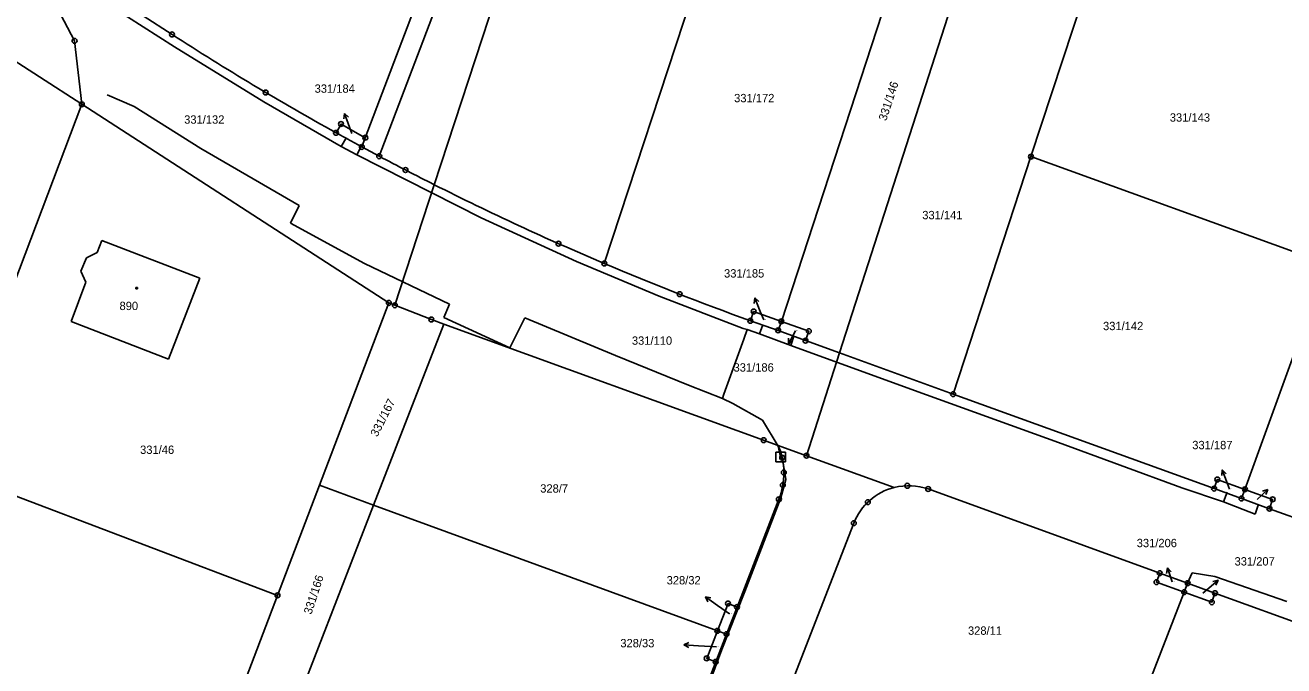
# Model space of a CAD drawing. Extents: x -770973 to -770265, y -1049936 to -1049427.
# Drawn here: x -770766.1 to -770637.6, y -1049695.4 to -1049630 of the extents above; entities that cross this region are included whole.
import ezdxf

# ---------------------------------------------------------------- set-up
doc = ezdxf.new("R2010")
doc.units = 0
for name, color, linetype in [('Vrstva 1', 7, 'Continuous'), ('Vrstva 13', 7, 'Continuous'), ('Vrstva 14', 7, 'Continuous'), ('Vrstva 15', 7, 'Continuous'), ('Vrstva 16', 7, 'Continuous'), ('Vrstva 25', 7, 'Continuous'), ('Vrstva 28', 7, 'Continuous'), ('Vrstva 50', 7, 'Continuous')]:
    doc.layers.add(name, color=color, linetype=linetype)

msp = doc.modelspace()

# ---------------------------------------------------------------- linework, layer by layer
at = {"layer": 'Vrstva 1'}
for p, q in [((-770724.33, -1049646.32), (-770694.96, -1049556.73)), ((-770703.1, -1049572.65), (-770729.95, -1049643.41)), ((-770718.4, -1049607.32), (-770731.37, -1049641.52)), ((-770693.08, -1049611.99), (-770706.97, -1049654.36)), ((-770675.2, -1049618.46), (-770688.89, -1049660.26)), ((-770682.94, -1049663.49), (-770669.15, -1049620.65)), ((-770663.4, -1049643.45), (-770657.33, -1049624.93)), ((-770761.06, -1049631.64), (-770763.19, -1049627.61)), ((-770751.11, -1049630.98), (-770754.04, -1049629.09)), ((-770770.92, -1049631.28), (-770760.32, -1049638.11)), ((-770760.32, -1049638.11), (-770761.06, -1049631.64)), ((-770774.43, -1049675.32), (-770760.32, -1049638.11)), ((-770728.97, -1049658.38), (-770760.32, -1049638.11)), ((-770733.85, -1049640.12), (-770734.36, -1049641.02)), ((-770734.36, -1049641.02), (-770731.73, -1049642.46)), ((-770731.37, -1049641.52), (-770733.85, -1049640.12)), ((-770731.73, -1049642.46), (-770731.37, -1049641.52)), ((-770729.95, -1049643.41), (-770731.73, -1049642.46)), ((-770671.35, -1049667.69), (-770663.4, -1049643.45)), ((-770633.21, -1049654.38), (-770663.4, -1049643.45)), ((-770728.36, -1049658.62), (-770724.33, -1049646.32)), ((-770758.27, -1049652.02), (-770758.74, -1049653.24)), ((-770748.28, -1049655.84), (-770758.27, -1049652.02)), ((-770759.84, -1049653.77), (-770760.41, -1049655.15)), ((-770758.74, -1049653.24), (-770759.84, -1049653.77)), ((-770760.41, -1049655.15), (-770759.91, -1049656.25)), ((-770641.55, -1049677.41), (-770633.21, -1049654.38)), ((-770759.91, -1049656.25), (-770761.42, -1049660.28)), ((-770751.46, -1049664.13), (-770748.28, -1049655.84)), ((-770736.06, -1049676.99), (-770728.97, -1049658.38)), ((-770728.97, -1049658.38), (-770728.36, -1049658.62)), ((-770724.63, -1049660.07), (-770728.36, -1049658.62)), ((-770761.42, -1049660.28), (-770751.46, -1049664.13)), ((-770723.36, -1049660.56), (-770724.63, -1049660.07)), ((-770692.05, -1049660.2), (-770691.72, -1049659.26)), ((-770689.22, -1049661.18), (-770692.05, -1049660.2)), ((-770691.72, -1049659.26), (-770688.89, -1049660.26)), ((-770688.89, -1049660.26), (-770689.22, -1049661.18)), ((-770686.08, -1049661.27), (-770688.89, -1049660.26)), ((-770723.36, -1049660.56), (-770730.53, -1049679.02)), ((-770689.2, -1049672.93), (-770723.36, -1049660.56)), ((-770689.22, -1049661.18), (-770686.42, -1049662.23)), ((-770686.42, -1049662.23), (-770686.08, -1049661.27)), ((-770682.94, -1049663.49), (-770686.42, -1049662.23)), ((-770686.32, -1049673.97), (-770682.94, -1049663.49)), ((-770671.35, -1049667.69), (-770682.94, -1049663.49)), ((-770644.7, -1049677.33), (-770671.35, -1049667.69)), ((-770686.32, -1049673.97), (-770689.2, -1049672.93)), ((-770677.36, -1049677.21), (-770686.32, -1049673.97)), ((-770740.34, -1049688.23), (-770774.43, -1049675.32)), ((-770740.34, -1049688.23), (-770736.06, -1049676.99)), ((-770736.06, -1049676.99), (-770730.53, -1049679.02)), ((-770644.7, -1049677.33), (-770644.37, -1049676.41)), ((-770644.37, -1049676.41), (-770641.55, -1049677.41)), ((-770650.25, -1049685.96), (-770673.89, -1049677.37)), ((-770641.9, -1049678.34), (-770644.7, -1049677.33)), ((-770641.55, -1049677.41), (-770641.9, -1049678.34)), ((-770639.05, -1049679.38), (-770641.9, -1049678.34)), ((-770641.55, -1049677.41), (-770638.72, -1049678.43)), ((-770730.53, -1049679.02), (-770738.31, -1049699.03)), ((-770730.53, -1049679.02), (-770695.42, -1049691.85)), ((-770693.41, -1049689.42), (-770689.14, -1049678.42)), ((-770638.72, -1049678.43), (-770639.05, -1049679.38)), ((-770639.05, -1049679.38), (-770620.83, -1049685.97)), ((-770681.49, -1049680.86), (-770688.8, -1049699.65)), ((-770650.58, -1049686.88), (-770650.25, -1049685.96)), ((-770650.25, -1049685.96), (-770647.4, -1049686.99)), ((-770650.58, -1049686.88), (-770647.75, -1049687.9)), ((-770647.4, -1049686.99), (-770647.75, -1049687.9)), ((-770647.4, -1049686.99), (-770644.61, -1049688)), ((-770744.59, -1049699.43), (-770740.34, -1049688.23)), ((-770656.82, -1049711.23), (-770647.75, -1049687.9)), ((-770647.75, -1049687.9), (-770644.93, -1049688.93)), ((-770644.61, -1049688), (-770644.93, -1049688.93)), ((-770644.61, -1049688), (-770615.41, -1049698.57)), ((-770695.42, -1049691.85), (-770694.33, -1049689.06)), ((-770693.41, -1049689.42), (-770694.49, -1049692.19)), ((-770694.33, -1049689.06), (-770693.41, -1049689.42)), ((-770696.51, -1049694.66), (-770695.42, -1049691.85)), ((-770694.49, -1049692.19), (-770695.59, -1049695.02)), ((-770695.42, -1049691.85), (-770694.49, -1049692.19)), ((-770703.19, -1049714.57), (-770695.59, -1049695.02)), ((-770695.59, -1049695.02), (-770696.51, -1049694.66))]:
    msp.add_line(p, q, dxfattribs=at)
for centre, radius, start, end in [((-770595.61, -1049390.55), 286.33, 237.1072, 241.0156), ((-770611.18, -1049420.91), 252.21, 241.9063, 243.344), ((-770591.07, -1049381.35), 296.59, 243.3013, 246.9978), ((-770591.46, -1049381.23), 296.55, 247.0756, 250.1716), ((-770695.48, -1049675.64), 6.84, 359.6799, 23.3403), ((-770695.86, -1049675.78), 7.22, 338.5329, 0.7838), ((-770675.9, -1049683.32), 6.28, 71.3097, 103.4103), ((-770675.85, -1049683.08), 6.06, 104.4378, 158.5012)]:
    msp.add_arc(centre, radius, start, end, dxfattribs=at)
at = {"layer": 'Vrstva 13'}
for p, q in [((-770732.74, -1049641.08), (-770732.97, -1049640.44)), ((-770690.69, -1049660.11), (-770691.04, -1049659.26)), ((-770643.13, -1049677.4), (-770643.34, -1049676.83)), ((-770645.84, -1049688.01), (-770645.43, -1049687.65)), ((-770694.18, -1049690.12), (-770695.42, -1049689.25)), ((-770695.52, -1049693.49), (-770697.34, -1049693.37))]:
    msp.add_line(p, q, dxfattribs=at)
at = {"layer": 'Vrstva 16'}
for p, q in [((-770733.5, -1049639.04), (-770733.55, -1049639.59)), ((-770732.97, -1049640.44), (-770733.5, -1049639.04)), ((-770733.5, -1049639.04), (-770733.09, -1049639.42)), ((-770691.61, -1049657.87), (-770691.65, -1049658.43)), ((-770691.04, -1049659.26), (-770691.61, -1049657.87)), ((-770691.61, -1049657.87), (-770691.19, -1049658.24)), ((-770687.46, -1049661.23), (-770688.17, -1049662.55)), ((-770688.17, -1049662.55), (-770688.15, -1049661.99)), ((-770688.17, -1049662.55), (-770687.71, -1049662.23)), ((-770643.86, -1049675.42), (-770643.92, -1049675.98)), ((-770643.34, -1049676.83), (-770643.86, -1049675.42)), ((-770643.86, -1049675.42), (-770643.45, -1049675.81)), ((-770640.29, -1049678.45), (-770639.21, -1049677.41)), ((-770639.21, -1049677.41), (-770639.74, -1049677.58)), ((-770639.21, -1049677.41), (-770639.4, -1049677.94)), ((-770649.47, -1049685.43), (-770649.55, -1049685.99)), ((-770648.98, -1049686.85), (-770649.47, -1049685.43)), ((-770649.47, -1049685.43), (-770649.07, -1049685.82)), ((-770645.43, -1049687.65), (-770644.3, -1049686.66)), ((-770644.3, -1049686.66), (-770644.84, -1049686.8)), ((-770644.3, -1049686.66), (-770644.51, -1049687.18)), ((-770695.42, -1049689.25), (-770696.65, -1049688.39)), ((-770696.65, -1049688.39), (-770696.38, -1049688.88)), ((-770696.65, -1049688.39), (-770696.1, -1049688.47)), ((-770698.84, -1049693.27), (-770698.32, -1049693.05)), ((-770697.34, -1049693.37), (-770698.84, -1049693.27)), ((-770698.84, -1049693.27), (-770698.35, -1049693.55))]:
    msp.add_line(p, q, dxfattribs=at)
at = {"layer": 'Vrstva 25'}
for p, q in [((-770754.79, -1049656.8), (-770754.64, -1049656.8)), ((-770754.79, -1049656.95), (-770754.79, -1049656.8)), ((-770754.64, -1049656.95), (-770754.79, -1049656.95)), ((-770754.64, -1049656.8), (-770754.64, -1049656.95))]:
    msp.add_line(p, q, dxfattribs=at)
at = {"layer": 'Vrstva 28'}
for centre, radius in [((-770751.11, -1049630.98), 0.25), ((-770761.06, -1049631.64), 0.25), ((-770761.06, -1049631.64), 0.005), ((-770751.11, -1049630.98), 0.005), ((-770741.55, -1049636.9), 0.25), ((-770741.55, -1049636.9), 0.005), ((-770760.32, -1049638.11), 0.25), ((-770760.32, -1049638.11), 0.005), ((-770734.36, -1049641.02), 0.25), ((-770734.36, -1049641.02), 0.005), ((-770733.85, -1049640.12), 0.25), ((-770733.85, -1049640.12), 0.005), ((-770731.73, -1049642.46), 0.25), ((-770731.37, -1049641.52), 0.25), ((-770731.37, -1049641.52), 0.005), ((-770731.73, -1049642.46), 0.005), ((-770729.95, -1049643.41), 0.25), ((-770729.95, -1049643.41), 0.005), ((-770663.4, -1049643.45), 0.25), ((-770663.4, -1049643.45), 0.005), ((-770727.27, -1049644.82), 0.25), ((-770727.27, -1049644.82), 0.005), ((-770711.64, -1049652.33), 0.25), ((-770711.64, -1049652.33), 0.005), ((-770706.97, -1049654.36), 0.25), ((-770706.97, -1049654.36), 0.005), ((-770699.27, -1049657.49), 0.25), ((-770699.27, -1049657.49), 0.005), ((-770728.97, -1049658.38), 0.25), ((-770728.97, -1049658.38), 0.005), ((-770728.36, -1049658.62), 0.25), ((-770728.36, -1049658.62), 0.005), ((-770691.72, -1049659.26), 0.25), ((-770724.63, -1049660.07), 0.25), ((-770724.63, -1049660.07), 0.005), ((-770692.05, -1049660.2), 0.25), ((-770692.05, -1049660.2), 0.005), ((-770691.72, -1049659.26), 0.005), ((-770688.89, -1049660.26), 0.25), ((-770688.89, -1049660.26), 0.005), ((-770689.22, -1049661.18), 0.25), ((-770689.22, -1049661.18), 0.005), ((-770686.08, -1049661.27), 0.25), ((-770686.08, -1049661.27), 0.005), ((-770686.42, -1049662.23), 0.25), ((-770686.42, -1049662.23), 0.005), ((-770671.35, -1049667.69), 0.25), ((-770671.35, -1049667.69), 0.005), ((-770690.69, -1049672.39), 0.25), ((-770690.69, -1049672.39), 0.005), ((-770688.8, -1049674.17), 0.25), ((-770688.8, -1049674.17), 0.005), ((-770686.32, -1049673.97), 0.25), ((-770686.32, -1049673.97), 0.005), ((-770688.64, -1049675.68), 0.25), ((-770688.64, -1049675.68), 0.005), ((-770688.74, -1049676.98), 0.25), ((-770688.74, -1049676.98), 0.005), ((-770676.03, -1049677.04), 0.25), ((-770676.03, -1049677.04), 0.005), ((-770644.7, -1049677.33), 0.25), ((-770644.37, -1049676.41), 0.25), ((-770644.37, -1049676.41), 0.005), ((-770689.14, -1049678.42), 0.25), ((-770673.89, -1049677.37), 0.25), ((-770673.89, -1049677.37), 0.005), ((-770644.7, -1049677.33), 0.005), ((-770641.9, -1049678.34), 0.25), ((-770641.9, -1049678.34), 0.005), ((-770641.55, -1049677.41), 0.25), ((-770641.55, -1049677.41), 0.005), ((-770638.72, -1049678.43), 0.25), ((-770689.14, -1049678.42), 0.005), ((-770680.06, -1049678.72), 0.25), ((-770680.06, -1049678.72), 0.005), ((-770639.05, -1049679.38), 0.25), ((-770639.05, -1049679.38), 0.005), ((-770638.72, -1049678.43), 0.005), ((-770681.49, -1049680.86), 0.25), ((-770681.49, -1049680.86), 0.005), ((-770650.25, -1049685.96), 0.25), ((-770650.25, -1049685.96), 0.005), ((-770650.58, -1049686.88), 0.25), ((-770650.58, -1049686.88), 0.005), ((-770647.4, -1049686.99), 0.25), ((-770647.4, -1049686.99), 0.005), ((-770740.34, -1049688.23), 0.25), ((-770740.34, -1049688.23), 0.005), ((-770647.75, -1049687.9), 0.25), ((-770647.75, -1049687.9), 0.005), ((-770644.61, -1049688), 0.25), ((-770644.61, -1049688), 0.005), ((-770694.33, -1049689.06), 0.25), ((-770694.33, -1049689.06), 0.005), ((-770693.41, -1049689.42), 0.25), ((-770693.41, -1049689.42), 0.005), ((-770644.93, -1049688.93), 0.25), ((-770644.93, -1049688.93), 0.005), ((-770695.42, -1049691.85), 0.25), ((-770695.42, -1049691.85), 0.005), ((-770694.49, -1049692.19), 0.25), ((-770694.49, -1049692.19), 0.005), ((-770696.51, -1049694.66), 0.25), ((-770696.51, -1049694.66), 0.005), ((-770695.59, -1049695.02), 0.25), ((-770695.59, -1049695.02), 0.005)]:
    msp.add_circle(centre, radius, dxfattribs=at)
at = {"layer": 'Vrstva 50'}
for p, q in [((-770750.85, -1049632.26), (-770764.12, -1049623.73)), ((-770741.74, -1049637.87), (-770750.85, -1049632.26)), ((-770757.73, -1049637.15), (-770754.98, -1049638.32)), ((-770754.98, -1049638.32), (-770748.18, -1049642.62)), ((-770733.83, -1049642.43), (-770741.74, -1049637.87)), ((-770733.83, -1049642.43), (-770733.29, -1049641.49)), ((-770748.18, -1049642.62), (-770738.14, -1049648.44)), ((-770732.23, -1049643.26), (-770733.83, -1049642.43)), ((-770732.23, -1049643.26), (-770731.82, -1049642.49)), ((-770719.55, -1049649.71), (-770732.23, -1049643.26)), ((-770738.14, -1049648.44), (-770739, -1049650.24)), ((-770709.79, -1049654.14), (-770719.55, -1049649.71)), ((-770739, -1049650.24), (-770731.47, -1049654.35)), ((-770731.47, -1049654.35), (-770722.79, -1049658.52)), ((-770701.37, -1049657.68), (-770709.79, -1049654.14)), ((-770692.78, -1049661), (-770701.37, -1049657.68)), ((-770722.79, -1049658.52), (-770723.37, -1049659.88)), ((-770723.37, -1049659.88), (-770716.61, -1049662.97)), ((-770716.61, -1049662.97), (-770715.08, -1049659.91)), ((-770715.08, -1049659.91), (-770705.83, -1049663.76)), ((-770692.39, -1049661.11), (-770692.78, -1049661)), ((-770692.39, -1049661.11), (-770692.71, -1049662.07)), ((-770691.13, -1049661.54), (-770692.39, -1049661.11)), ((-770691.13, -1049661.54), (-770690.79, -1049660.6)), ((-770687.93, -1049662.71), (-770691.13, -1049661.54)), ((-770694.75, -1049667.7), (-770692.71, -1049662.07)), ((-770687.93, -1049662.71), (-770687.61, -1049661.78)), ((-770675.3, -1049667.31), (-770687.93, -1049662.71)), ((-770705.83, -1049663.76), (-770698.37, -1049666.76)), ((-770698.37, -1049666.76), (-770694.9, -1049668.12)), ((-770694.9, -1049668.12), (-770694.75, -1049667.7)), ((-770660.59, -1049672.61), (-770675.3, -1049667.31)), ((-770694.9, -1049668.12), (-770693.84, -1049668.64)), ((-770693.84, -1049668.64), (-770690.81, -1049670.35)), ((-770690.81, -1049670.35), (-770689.22, -1049672.99)), ((-770689.22, -1049672.99), (-770688.96, -1049674.1)), ((-770648.01, -1049677.26), (-770660.59, -1049672.61)), ((-770688.46, -1049673.6), (-770689.46, -1049673.6)), ((-770689.46, -1049673.6), (-770689.46, -1049674.6)), ((-770688.96, -1049674.1), (-770688.69, -1049674.72)), ((-770688.46, -1049674.6), (-770688.46, -1049673.6)), ((-770689.46, -1049674.6), (-770688.46, -1049674.6)), ((-770688.69, -1049674.72), (-770688.43, -1049676.41)), ((-770688.43, -1049676.41), (-770688.93, -1049678.27)), ((-770688.93, -1049678.27), (-770692.61, -1049687.83)), ((-770643.75, -1049678.68), (-770648.01, -1049677.26)), ((-770643.36, -1049677.7), (-770643.75, -1049678.68)), ((-770640.52, -1049679.93), (-770643.75, -1049678.68)), ((-770640.18, -1049678.93), (-770640.52, -1049679.93)), ((-770646.93, -1049685.93), (-770647.41, -1049686.98)), ((-770644.63, -1049686.31), (-770646.93, -1049685.93)), ((-770637.26, -1049688.86), (-770644.63, -1049686.31)), ((-770692.61, -1049687.83), (-770694.98, -1049693.75)), ((-770694.98, -1049693.75), (-770698.33, -1049702.78))]:
    msp.add_line(p, q, dxfattribs=at)

# ---------------------------------------------------------------- texts
at = {"layer": 'Vrstva 14'}
for s, rotation, p in [('331/146', 72, (-770678.18, -1049639.86)), ('331/167', 63, (-770730.15, -1049672.11)), ('331/166', 72, (-770736.88, -1049690.23))]:
    msp.add_text(s, height=0.85, rotation=rotation, dxfattribs=at).set_placement(p)
for s, height, p in [('331/172', 0.85, (-770693.71, -1049637.9)), ('331/132', 0.85, (-770749.87, -1049640.09)), ('331/143', 0.85, (-770649.22, -1049639.88)), ('331/184', 0.05, (-770732.74, -1049641.08)), ('331/141', 0.85, (-770674.5, -1049649.84)), ('331/185', 0.05, (-770690.69, -1049660.11)), ('331/142', 0.85, (-770656.04, -1049661.16)), ('331/186', 0.05, (-770687.46, -1049661.23)), ('331/110', 0.85, (-770704.15, -1049662.65)), ('331/46', 0.85, (-770754.37, -1049673.79)), ('328/7', 0.85, (-770713.51, -1049677.74)), ('331/187', 0.05, (-770643.13, -1049677.4)), ('331/188', 0.05, (-770640.29, -1049678.45)), ('331/206', 0.05, (-770648.98, -1049686.85)), ('331/207', 0.05, (-770645.84, -1049688.01)), ('328/32', 0.05, (-770694.18, -1049690.12)), ('328/11', 0.85, (-770669.83, -1049692.25)), ('328/33', 0.05, (-770695.52, -1049693.49))]:
    msp.add_text(s, height=height, dxfattribs=at).set_placement(p)
at = {"layer": 'Vrstva 15'}
msp.add_text('890', height=0.85, dxfattribs=at).set_placement((-770756.47, -1049659.11))
at = {"layer": 'Vrstva 16'}
for s, p in [('331/184', (-770736.55, -1049636.93)), ('331/185', (-770694.74, -1049655.79)), ('331/186', (-770693.77, -1049665.39)), ('331/187', (-770646.93, -1049673.31)), ('331/206', (-770652.6, -1049683.31)), ('331/207', (-770642.61, -1049685.18)), ('328/32', (-770700.6, -1049687.11)), ('328/33', (-770705.33, -1049693.53))]:
    msp.add_text(s, height=0.85, dxfattribs=at).set_placement(p)

doc.saveas('drawing.dxf')
